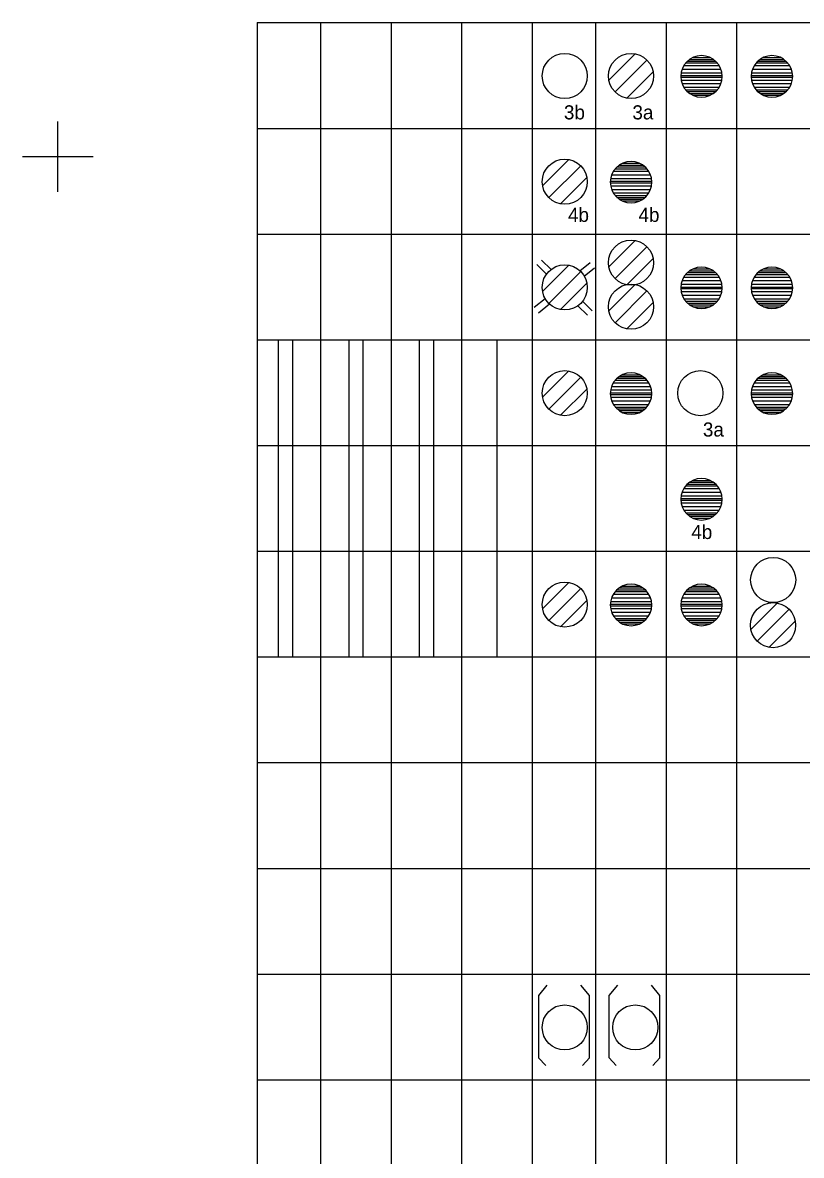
# Model space of a CAD drawing. Extents: x -28 to 822, y 61 to 665.
# Drawn here: x -28.2 to 82.3, y 221 to 381.7 of the extents above; entities that cross this region are included whole.
import ezdxf

# ---------------------------------------------------------------- set-up
doc = ezdxf.new("R2010")
doc.units = 0
for name, color, linetype in [('KOLEJIŠTĚ', 7, 'Continuous'), ('nové', 7, 'Continuous'), ('Vrstva 60', 7, 'Continuous')]:
    doc.layers.add(name, color=color, linetype=linetype)

# ---------------------------------------------------------------- blocks, each defined once
blk = doc.blocks.new('ZT95')
for p, q in [((2.793, 4.073), (0.927, 2.207)), ((3.631, 3.631), (1.369, 1.369)), ((4.073, 2.793), (2.207, 0.927))]:
    blk.add_line(p, q)
blk.add_circle((2.5, 2.5), 1.6)
blk = doc.blocks.new('HR6')
for p, q in [((-1.75, 1.49), (1.75, 1.49)), ((-1.56, 1.69), (1.56, 1.69)), ((-1.3, 1.89), (1.3, 1.89)), ((-0.95, 2.09), (0.95, 2.09)), ((-2.26, 0.4), (2.26, 0.4)), ((-2.2, 0.09), (2.2, 0.09)), ((-2.16, 0.8), (2.16, 0.8)), ((-1.96, 1.2), (1.96, 1.2)), ((-2.26, -0.4), (2.26, -0.4)), ((-2.2, -0.09), (2.2, -0.09)), ((-2.16, -0.8), (2.16, -0.8)), ((-1.96, -1.2), (1.96, -1.2)), ((-1.75, -1.49), (1.75, -1.49)), ((-1.56, -1.69), (1.56, -1.69)), ((-1.3, -1.89), (1.3, -1.89)), ((-0.95, -2.09), (0.95, -2.09))]:
    blk.add_line(p, q)
for start, end in [(0, 180), (180, 0)]:
    blk.add_arc((0, 0), 2.3, start, end)
blk = doc.blocks.new('ZT94')
at = {"xscale": 0.6400000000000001, "yscale": 0.6400000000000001}
blk.add_blockref('HR6', (2.5, 2.5), dxfattribs=at)

msp = doc.modelspace()

# ---------------------------------------------------------------- linework, layer by layer
for p, q in [((5.07, 381.74), (5.07, 111.74)), ((5.07, 381.74), (540.62, 381.74)), ((5.07, 381.74), (293.12, 381.74)), ((5.07, 381.74), (293.12, 381.74)), ((14.09, 381.74), (14.09, 111.74)), ((24.09, 381.74), (24.09, 111.74)), ((34.09, 381.74), (34.09, 111.74)), ((44.09, 381.74), (44.09, 336.74)), ((53.12, 381.74), (53.12, 111.74)), ((63.12, 381.74), (63.12, 111.74)), ((73.12, 381.74), (73.12, 111.74)), ((5.07, 366.74), (292.72, 366.74)), ((5.07, 351.74), (540.62, 351.74)), ((46.14, 346.05), (44.78, 347.41)), ((46.79, 346.71), (45.43, 348.06)), ((50.89, 346.54), (52.33, 347.7)), ((51.5, 345.78), (52.95, 346.94)), ((44.39, 341.35), (45.95, 342.6)), ((45, 340.58), (46.56, 341.83)), ((51.98, 340.21), (50.61, 341.58)), ((52.63, 340.86), (51.27, 342.22)), ((5.07, 336.74), (540.62, 336.74)), ((5.07, 336.74), (293.12, 336.74)), ((5.07, 336.74), (293.12, 336.74)), ((44.09, 336.74), (44.09, 111.74)), ((5.07, 321.74), (292.72, 321.74)), ((5.07, 306.74), (540.62, 306.74)), ((5.07, 291.74), (540.62, 291.74)), ((5.07, 276.74), (292.72, 276.74)), ((5.07, 261.74), (540.62, 261.74)), ((5.07, 246.74), (540.62, 246.74)), ((5.07, 246.74), (540.62, 246.74)), ((45.05, 243.68), (46.25, 245.15)), ((52.23, 243.68), (51.03, 245.15)), ((55.05, 243.68), (56.25, 245.15)), ((62.23, 243.68), (61.03, 245.15)), ((45.05, 234.87), (45.05, 243.68)), ((52.23, 234.87), (52.23, 243.68)), ((55.05, 234.87), (55.05, 243.68)), ((62.23, 234.87), (62.23, 243.68)), ((45.03, 234.84), (46.03, 233.76)), ((52.25, 234.84), (51.25, 233.76)), ((55.03, 234.84), (56.03, 233.76)), ((62.25, 234.84), (61.25, 233.76)), ((5.07, 231.74), (292.72, 231.74))]:
    msp.add_line(p, q)
for centre in [(48.74, 374.17), (67.98, 329.17), (78.31, 302.66), (48.74, 239.17), (58.74, 239.17)]:
    msp.add_circle(centre, 3.2)
at = {"layer": 'nové'}
for p, q in [((8.09, 336.74), (8.09, 321.74)), ((10.09, 336.74), (10.09, 321.74)), ((18.09, 336.74), (18.09, 321.74)), ((20.09, 336.74), (20.09, 321.74)), ((28.09, 336.74), (28.09, 321.74)), ((30.09, 336.74), (30.09, 321.74)), ((39.09, 336.74), (39.09, 321.74)), ((8.09, 321.74), (8.09, 306.74)), ((10.09, 321.74), (10.09, 306.74)), ((18.09, 321.74), (18.09, 306.74)), ((20.09, 321.74), (20.09, 306.74)), ((28.09, 321.74), (28.09, 306.74)), ((30.09, 321.74), (30.09, 306.74)), ((39.09, 321.74), (39.09, 306.74)), ((8.09, 306.74), (8.09, 291.74)), ((10.09, 306.74), (10.09, 291.74)), ((18.09, 306.74), (18.09, 291.74)), ((20.09, 306.74), (20.09, 291.74)), ((28.09, 306.74), (28.09, 291.74)), ((30.09, 306.74), (30.09, 291.74)), ((39.09, 306.74), (39.09, 291.74))]:
    msp.add_line(p, q, dxfattribs=at)
at = {"layer": 'Vrstva 60'}
for p, q in [((-23.19, 357.73), (-23.19, 367.73)), ((-28.19, 362.73), (-18.19, 362.73))]:
    msp.add_line(p, q, dxfattribs=at)

# ---------------------------------------------------------------- block references
at = {"layer": 'KOLEJIŠTĚ', "xscale": 2, "yscale": 2}
for name, p in [('ZT95', (53.14, 369.17)), ('ZT94', (63.14, 369.11)), ('ZT94', (73.14, 369.11)), ('ZT95', (43.74, 354.17)), ('ZT94', (53.14, 354.11)), ('ZT95', (53.14, 342.68)), ('ZT95', (43.74, 339.17)), ('ZT94', (63.14, 339.11)), ('ZT94', (73.14, 339.11)), ('ZT95', (53.14, 336.43)), ('ZT95', (43.74, 324.17)), ('ZT94', (53.14, 324.11)), ('ZT94', (73.14, 324.11)), ('ZT94', (63.14, 309.11)), ('ZT95', (43.74, 294.17)), ('ZT94', (53.14, 294.11)), ('ZT94', (63.14, 294.11)), ('ZT95', (73.3, 291.24))]:
    msp.add_blockref(name, p, dxfattribs=at)

# ---------------------------------------------------------------- texts
for s, p in [('3b', (48.62, 368.01)), ('3a', (58.34, 368.01)), ('4b', (49.2, 353.47)), ('4b', (59.2, 353.47)), ('3a', (68.34, 323.01)), ('4b', (66.7, 308.47))]:
    msp.add_text(s, height=2).set_placement(p)

doc.saveas('drawing.dxf')
